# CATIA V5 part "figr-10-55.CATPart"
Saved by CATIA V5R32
Part number: Part1
Bounding box of the stored display mesh (mm): x -101.896 to 127.212, y -67.72 to 67.298, z 0 to 0
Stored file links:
  D:\PROJECTS\Project 2022\CATIA V5 6R 2022\Resources\Part Files\c10_catia_v5_6r2022_prt\c10_catia_v5_6r2022_prt\figr-10-55.CATPart
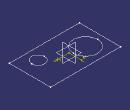
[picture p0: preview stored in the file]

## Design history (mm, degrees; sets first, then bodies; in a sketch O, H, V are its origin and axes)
Body1 (main body)
  Sketch1 on xy-plane, origin (0, 0, 0), H (1, 0, 0), V (0, 1, 0)
    line L1 (-101.8963, 67.298) -> (127.2122, 67.298)
    line L2 (127.2122, 67.298) -> (127.2122, -67.7199)
    line L3 (127.2122, -67.7199) -> (-101.8963, -67.7199)
    line L4 (-101.8963, -67.7199) -> (-101.8963, 67.298)
    horizontal: L1 H, L3 H
    vertical: L2 V, L4 V
  Sketch2 on xy-plane, origin (0, 0, 0), H (1, 0, 0), V (0, 1, 0)
    circle A1 centre (-45.2964, 9.2296) radius 39.3004
    circle A2 centre (71.0804, -29.9585) radius 20.9926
